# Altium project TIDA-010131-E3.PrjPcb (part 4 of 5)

## Sheet TIDA-010131-E3_USB.SchDoc: FT4232HQ_USB
size 431 x 279 mm; Date: Not shown in title block; ApprovedBy: Not shown in title block; CheckedBy: Not shown in title block; Author: Not shown in title block; CompanyName: Not shown in title block; DrawnBy: Avinash N; Engineer: Not shown in title block; Organization: Not shown in title block; Address1: Not shown in title block; Address2: Not shown in title block; Address3: Not shown in title block; Address4: Not shown in title block; DocumentNumber: 1; Revision: Use project parameter SCH_Rev; SheetNumber: 7; SheetTotal: 9; PageSetup: Record=PageOptions¦CenterHorizontal=True¦CenterVertical=True¦PrintScale=1.00¦XCorrection=1.00¦YCorrection=1.00¦PrintKind=0¦BorderSize=5000000¦LeftOffset=0¦BottomOffset=0¦Orientation=2¦PaperLength=1000¦PaperWidth=1000¦Scale=100¦PaperSource=15¦PrintQuality=600¦MediaType=1¦DitherType=10¦PaperKind=Letter¦PrintScaleMode=1
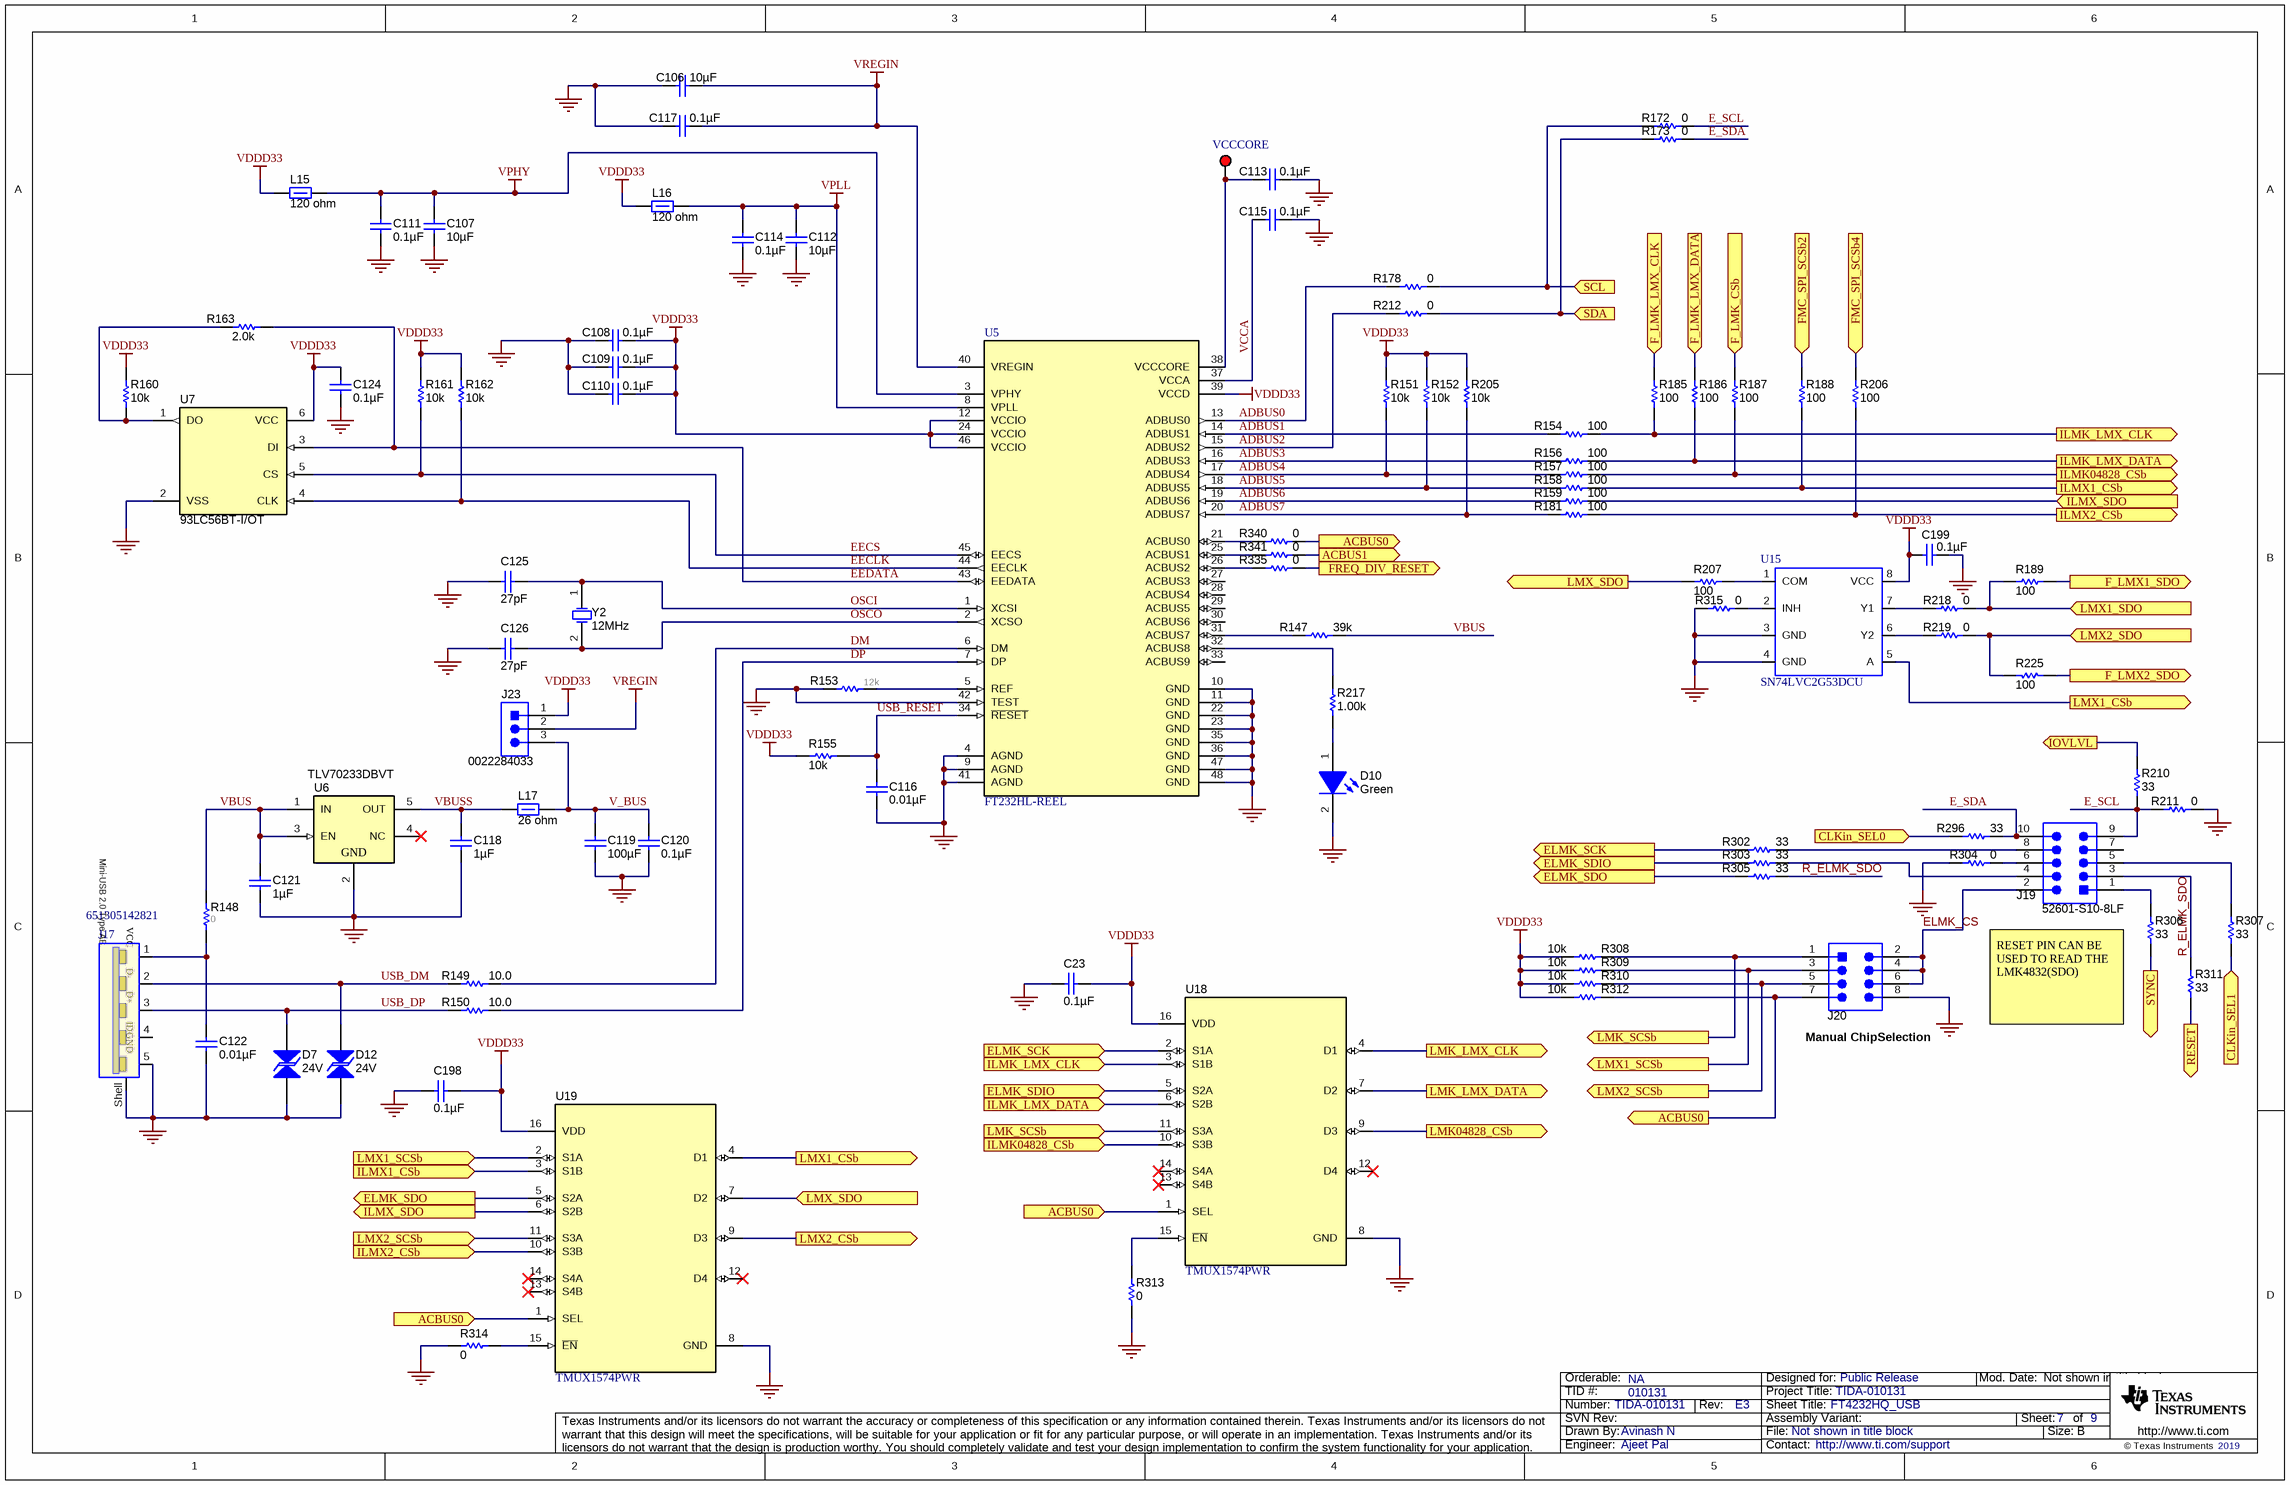
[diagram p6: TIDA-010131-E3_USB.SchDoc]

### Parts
C23  ValueDisplayed: 0.1µF  [0603]  (hidden comment: C0603C104J3RACTU)
C106  ValueDisplayed: 10µF  [0603]  (hidden comment: GRM188R61A106ME69D)
C107  ValueDisplayed: 10µF  [0603]  (hidden comment: GRM188R61A106ME69D)
C108  ValueDisplayed: 0.1µF  [0603]  (hidden comment: C0603C104J3RACTU)
C109  ValueDisplayed: 0.1µF  [0603]  (hidden comment: C0603C104J3RACTU)
C110  ValueDisplayed: 0.1µF  [0603]  (hidden comment: C0603C104J3RACTU)
C111  ValueDisplayed: 0.1µF  [0603]  (hidden comment: C0603C104J3RACTU)
C112  ValueDisplayed: 10µF  [0603]  (hidden comment: GRM188R61A106ME69D)
C113  ValueDisplayed: 0.1µF  [0603]  (hidden comment: C0603C104J3RACTU)
C114  ValueDisplayed: 0.1µF  [0603]  (hidden comment: C0603C104J3RACTU)
C115  ValueDisplayed: 0.1µF  [0603]  (hidden comment: C0603C104J3RACTU)
C116  ValueDisplayed: 0.01µF  [0402]  (hidden comment: GRM155R71E103KA01D)
C117  ValueDisplayed: 0.1µF  [0603]  (hidden comment: C0603C104J3RACTU)
C118  ValueDisplayed: 1µF  [0603]  (hidden comment: C1608X7R1C105K080AC)
C119  ValueDisplayed: 100µF  [1210_270]  (hidden comment: GRM32ER61A107ME20L)
C120  ValueDisplayed: 0.1µF  [0603]  (hidden comment: C0603C104J3RACTU)
C121  ValueDisplayed: 1µF  [0603]  (hidden comment: C1608X7R1C105K080AC)
C122  ValueDisplayed: 0.01µF  [0402]  (hidden comment: GRM155R71E103KA01D)
C124  ValueDisplayed: 0.1µF  [0603]  (hidden comment: C0603C104J3RACTU)
C125  ValueDisplayed: 27pF  [0603]  (hidden comment: GRM1885C2A270JA01D)
C126  ValueDisplayed: 27pF  [0603]  (hidden comment: GRM1885C2A270JA01D)
C198  ValueDisplayed: 0.1µF  [0603]  (hidden comment: C0603C104J3RACTU)
C199  ValueDisplayed: 0.1µF  [0603]  (hidden comment: C0603C104J3RACTU)
D7  value 24V  [PGB1_0603]  (hidden comment: PGB1010603MR)
D10  value Green  [LTST-C191_Green]  (hidden comment: LTST-C191TGKT)
D12  value 24V  [PGB1_0603]  (hidden comment: PGB1010603MR)
J17  651305142821  [651305142821]
J19  52601-S10-8LF  [FCI_52601-S10-8LF]
J20  TSW-104-07-G-D  [TSW-104-07-G-D]  (value not drawn)
J23  0022284033  [Molex_0022284033]
L15  ValueDisplayed: 120 ohm  [1206]  (hidden comment: BLM31PG121SN1L)
L16  ValueDisplayed: 120 ohm  [1206]  (hidden comment: BLM31PG121SN1L)
L17  ValueDisplayed: 26 ohm  [0603]  (hidden comment: BLM18SG260TN1D)
R147  ValueDisplayed: 39k  [0603]  (hidden comment: CRCW060339K0JNEA)
R148  value 0  [0603]  (hidden comment: CRCW06030000Z0EA)
R149  ValueDisplayed: 10.0  [0603]  (hidden comment: CRCW060310R0FKEAHP)
R150  ValueDisplayed: 10.0  [0603]  (hidden comment: CRCW060310R0FKEAHP)
R151  ValueDisplayed: 10k  [0603]  (hidden comment: CRCW060310K0JNEA)
R152  ValueDisplayed: 10k  [0603]  (hidden comment: CRCW060310K0JNEA)
R153  value 12k  [0603]  (hidden comment: CRCW060312K0JNEA)
R154  ValueDisplayed: 100  [0603]  (hidden comment: CRCW0603100RFKEA)
R155  ValueDisplayed: 10k  [0603]  (hidden comment: CRCW060310K0JNEA)
R156  ValueDisplayed: 100  [0603]  (hidden comment: CRCW0603100RFKEA)
R157  ValueDisplayed: 100  [0603]  (hidden comment: CRCW0603100RFKEA)
R158  ValueDisplayed: 100  [0603]  (hidden comment: CRCW0603100RFKEA)
R159  ValueDisplayed: 100  [0603]  (hidden comment: CRCW0603100RFKEA)
R160  ValueDisplayed: 10k  [0603]  (hidden comment: CRCW060310K0JNEA)
R161  ValueDisplayed: 10k  [0603]  (hidden comment: CRCW060310K0JNEA)
R162  ValueDisplayed: 10k  [0603]  (hidden comment: CRCW060310K0JNEA)
R163  ValueDisplayed: 2.0k  [0603]  (hidden comment: CRCW06032K00JNEA)
R172  ValueDisplayed: 0  [0402]  (hidden comment: CRCW04020000Z0ED)
R173  ValueDisplayed: 0  [0402]  (hidden comment: CRCW04020000Z0ED)
R178  ValueDisplayed: 0  [0603]  (hidden comment: CRCW06030000Z0EA)
R181  ValueDisplayed: 100  [0603]  (hidden comment: CRCW0603100RFKEA)
R185  ValueDisplayed: 100  [0603]  (hidden comment: CRCW0603100RFKEA)
R186  ValueDisplayed: 100  [0603]  (hidden comment: CRCW0603100RFKEA)
R187  ValueDisplayed: 100  [0603]  (hidden comment: CRCW0603100RFKEA)
R188  ValueDisplayed: 100  [0603]  (hidden comment: CRCW0603100RFKEA)
R189  ValueDisplayed: 100  [0603]  (hidden comment: CRCW0603100RFKEA)
R205  ValueDisplayed: 10k  [0603]  (hidden comment: CRCW060310K0JNEA)
R206  ValueDisplayed: 100  [0603]  (hidden comment: CRCW0603100RFKEA)
R207  ValueDisplayed: 100  [0603]  (hidden comment: CRCW0603100RFKEA)
R210  ValueDisplayed: 33  [0603]  (hidden comment: CRCW060333R0JNEA)
R211  ValueDisplayed: 0  [0603]  (hidden comment: CRCW06030000Z0EA)
R212  ValueDisplayed: 0  [0603]  (hidden comment: CRCW06030000Z0EA)
R217  ValueDisplayed: 1.00k  [0603]  (hidden comment: CRCW06031K00FKEA)
R218  ValueDisplayed: 0  [0402]  (hidden comment: CRCW04020000Z0ED)
R219  ValueDisplayed: 0  [0402]  (hidden comment: CRCW04020000Z0ED)
R225  ValueDisplayed: 100  [0603]  (hidden comment: CRCW0603100RFKEA)
R296  ValueDisplayed: 33  [0603]  (hidden comment: CRCW060333R0JNEA)
R302  ValueDisplayed: 33  [0603]  (hidden comment: CRCW060333R0JNEA)
R303  ValueDisplayed: 33  [0603]  (hidden comment: CRCW060333R0JNEA)
R304  ValueDisplayed: 0  [0603]  (hidden comment: CRCW06030000Z0EA)
R305  ValueDisplayed: 33  [0603]  (hidden comment: CRCW060333R0JNEA)
R306  ValueDisplayed: 33  [0603]  (hidden comment: CRCW060333R0JNEA)
R307  ValueDisplayed: 33  [0603]  (hidden comment: CRCW060333R0JNEA)
R308  ValueDisplayed: 10k  [0603]  (hidden comment: CRCW060310K0JNEA)
R309  ValueDisplayed: 10k  [0603]  (hidden comment: CRCW060310K0JNEA)
R310  ValueDisplayed: 10k  [0603]  (hidden comment: CRCW060310K0JNEA)
R311  ValueDisplayed: 33  [0603]  (hidden comment: CRCW060333R0JNEA)
R312  ValueDisplayed: 10k  [0603]  (hidden comment: CRCW060310K0JNEA)
R313  ValueDisplayed: 0  [0402]  (hidden comment: CRCW04020000Z0ED)
R314  ValueDisplayed: 0  [0402]  (hidden comment: CRCW04020000Z0ED)
R315  ValueDisplayed: 0  [0603]  (hidden comment: CRCW06030000Z0EA)
R335  ValueDisplayed: 0  [0402]  (hidden comment: CRCW04020000Z0ED)
R340  ValueDisplayed: 0  [0402]  (hidden comment: CRCW04020000Z0ED)
R341  ValueDisplayed: 0  [0402]  (hidden comment: CRCW04020000Z0ED)
U5  FT232HL-REEL  [LQFP-48_N]
U6  TLV70233DBVT  [DBV0005A_N]
U7  93LC56BT-I/OT  [SOT-23-6]
U15  SN74LVC2G53DCU  [VSSOP8]
U18  TMUX1574PWR  [PW0016A_N]
U19  TMUX1574PWR  [PW0016A_N]
VCCCORE  5000  [Keystone5000]  (value not drawn)
Y2  Frequency: 12MHz  [XTAL_ABM3]  (hidden comment: ABM3-12.000MHZ-B2-T)

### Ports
ACBUS0 (in), ACBUS0 (out), ACBUS1 (out), CLKin_SEL0 (in), CLKin_SEL1 (in), ELMK_SCK (in), ELMK_SCK (out), ELMK_SDIO (in), ELMK_SDIO (out), ELMK_SDO (out), F_LMK_CSb (in), F_LMK_LMX_CLK (in), F_LMK_LMX_DATA (in), F_LMX1_SDO (out), F_LMX2_SDO (out), FMC_SPI_SCSb2 (in), FMC_SPI_SCSb4 (in), FREQ_DIV_RESET (out), ILMK04828_CSb (in), ILMK04828_CSb (out), ILMK_LMX_CLK (in), ILMK_LMX_CLK (out), ILMK_LMX_DATA (in), ILMK_LMX_DATA (out), ILMX1_CSb (in), ILMX1_CSb (out), ILMX2_CSb (in), ILMX2_CSb (out), ILMX_SDO (in), ILMX_SDO (out), IOVLVL (out), LMK04828_CSb (out), LMK_LMX_CLK (out), LMK_LMX_DATA (out), LMK_SCSb (in), LMK_SCSb (out), LMX1_CSb (out), LMX1_SCSb (in), LMX1_SCSb (out), LMX1_SDO (in), LMX2_CSb (out), LMX2_SCSb (in), LMX2_SCSb (out), LMX2_SDO (in), LMX_SDO (in), LMX_SDO (out), RESET (out), SCL (in), SDA (in), SYNC (out)

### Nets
GND: C23.1 C106.2 C107.1 C108.2 C109.2 C110.2 C111.2 C112.2 C113.1 C114.2 C115.1 C116.2 C117.2 C118.2 C119.2 C120.1 C121.2 C122.2 C124.1 C125.1 C126.2 C198.1 C199.2 D7.1 D10.2(K) D12.1 J17.5(GND) J17.Shell J20.8 R153.2 R211.2 R304.1 R313.1 R314.1 R315.1 U5.4(AGND) U5.9(AGND) U5.10(GND) U5.11(GND) U5.22(GND) U5.23(GND) U5.35(GND) U5.36(GND) U5.41(AGND) U5.42(TEST) U5.47(GND) U5.48(GND) U6.2(GND) U7.2(VSS) U15.3(GND) U15.4(GND) U18.8(GND) U19.8(GND)
VDDD33: C23.2 C108.1 C109.1 C110.1 C124.2 C198.2 C199.1 J23.1 L15.1 L16.1 R151.2 R152.2 R155.2 R160.2 R161.2 R162.2 R205.2 R308.1 R309.1 R310.1 R312.1 U5.12(VCCIO) U5.24(VCCIO) U5.39(VCCD) U5.46(VCCIO) U7.6(VCC) U15.8(VCC) U18.16(VDD) U19.16(VDD)
VPHY: C107.2 C111.1 L15.2 U5.3(VPHY)
VPLL: C112.1 C114.1 L16.2 U5.8(VPLL)
VREGIN: C106.1 C117.1 J23.2 U5.40(VREGIN)
ACBUS0: J20.7 R312.2 R340.1 U18.1(SEL) U19.1(SEL) ; port ACBUS0
ACBUS1: R341.1 ; port ACBUS1
ADBUS0: R178.1 U5.13(ADBUS0)
ADBUS1: R154.1 U5.14(ADBUS1)
ADBUS2: R212.1 U5.15(ADBUS2)
ADBUS3: R156.1 U5.16(ADBUS3)
ADBUS4: R151.1 R157.1 U5.17(ADBUS4)
ADBUS5: R152.1 R158.1 U5.18(ADBUS5)
ADBUS6: R159.1 U5.19(ADBUS6)
ADBUS7: R181.1 R205.1 U5.20(ADBUS7)
CLKin_SEL0: R296.2 ; port CLKin_SEL0
CLKin_SEL1: R307.1 ; port CLKin_SEL1
DM: R149.2 U5.6(DM)
DP: R150.2 U5.7(DP)
E_SCL: J19.9 R172.2 R210.1 R211.1
E_SDA: J19.10 R173.2 R296.1
EECLK: R162.1 U5.44(EECLK) U7.4(CLK)
EECS: R161.1 U5.45(EECS) U7.5(CS)
EEDATA: R163.2 U5.43(EEDATA) U7.3(DI)
ELMK_CS: J19.2 J20.2 J20.4 J20.6
ELMK_SCK: R302.1 U18.2(S1A) ; port ELMK_SCK
ELMK_SDIO: R303.1 U18.5(S2A) ; port ELMK_SDIO
ELMK_SDO: R305.1 U19.5(S2A) ; port ELMK_SDO
F_LMK_CSb: R187.2 ; port F_LMK_CSb
F_LMK_LMX_CLK: R185.2 ; port F_LMK_LMX_CLK
F_LMK_LMX_DATA: R186.2 ; port F_LMK_LMX_DATA
F_LMX1_SDO: R189.2 ; port F_LMX1_SDO
F_LMX2_SDO: R225.2 ; port F_LMX2_SDO
FMC_SPI_SCSb2: R188.2 ; port FMC_SPI_SCSb2
FMC_SPI_SCSb4: R206.2 ; port FMC_SPI_SCSb4
FREQ_DIV_RESET: R335.1 ; port FREQ_DIV_RESET
ILMK04828_CSb: R157.2 R187.1 U18.10(S3B) ; port ILMK04828_CSb
ILMK_LMX_CLK: R154.2 R185.1 U18.3(S1B) ; port ILMK_LMX_CLK
ILMK_LMX_DATA: R156.2 R186.1 U18.6(S2B) ; port ILMK_LMX_DATA
ILMX1_CSb: R158.2 R188.1 U19.3(S1B) ; port ILMX1_CSb
ILMX2_CSb: R181.2 R206.1 U19.10(S3B) ; port ILMX2_CSb
ILMX_SDO: R159.2 U19.6(S2B) ; port ILMX_SDO
IOVLVL: R210.2 ; port IOVLVL
LMK04828_CSb: U18.9(D3) ; port LMK04828_CSb
LMK_LMX_CLK: U18.4(D1) ; port LMK_LMX_CLK
LMK_LMX_DATA: U18.7(D2) ; port LMK_LMX_DATA
LMK_SCSb: J20.1 R308.2 U18.11(S3A) ; port LMK_SCSb
LMX1_CSb: U15.5(A) U19.4(D1) ; port LMX1_CSb
LMX1_SCSb: J20.3 R309.2 U19.2(S1A) ; port LMX1_SCSb
LMX1_SDO: R189.1 R218.2 ; port LMX1_SDO
LMX2_CSb: U19.9(D3) ; port LMX2_CSb
LMX2_SCSb: J20.5 R310.2 U19.11(S3A) ; port LMX2_SCSb
LMX2_SDO: R219.2 R225.1 ; port LMX2_SDO
LMX_SDO: R207.2 U19.7(D2) ; port LMX_SDO
OSCI: C125.2 U5.1(XCSI) Y2.1(OSC1)
OSCO: C126.1 U5.2(XCSO) Y2.2(OSC2)
R_ELMK_SDO: J19.3 R305.2 R311.2
RESET: R311.1 ; port RESET
SCL: R172.1 R178.2 ; port SCL
SDA: R173.1 R212.2 ; port SDA
SYNC: R306.1 ; port SYNC
USB_DM: D12.2 J17.2(D-) R149.1
USB_DP: D7.2 J17.3(D+) R150.1
USB_RESET: C116.1 R155.1 U5.34(~{RESET})
V_BUS: C119.1 C120.2 J23.3 L17.2
VBUS: C121.1 R147.2 R148.2 U6.1(IN) U6.3(EN)
VBUSS: C118.1 L17.1 U6.5(OUT)
VCCA: C115.2 U5.37(VCCA)
NetC113_2: C113.2 U5.38(VCCCORE) VCCCORE.1
NetC122_1: C122.1 J17.1(VCC) R148.1
NetD10_1: D10.1(A) R217.1
NetJ19_1: J19.1 R306.2
NetJ19_4: J19.4 R303.2
NetJ19_5: J19.5 R307.2
NetJ19_6: J19.6 R304.2
NetJ19_8: J19.8 R302.2
NetR147_1: R147.1 U5.31(ACBUS7)
NetR153_1: R153.1 U5.5(REF)
NetR160_1: R160.1 R163.1 U7.1(DO)
NetR207_1: R207.1 U15.1(COM)
NetR217_2: R217.2 U5.32(ACBUS8)
NetR218_1: R218.1 U15.7(Y1)
NetR219_1: R219.1 U15.6(Y2)
NetR313_2: R313.2 U18.15(~{EN})
NetR314_2: R314.2 U19.15(~{EN})
NetR315_2: R315.2 U15.2(INH)
NetR335_2: R335.2 U5.26(ACBUS2)
NetR340_2: R340.2 U5.21(ACBUS0)
NetR341_2: R341.2 U5.25(ACBUS1)

Not connected (* = marked no-connect by the designer): J17 4(ID); J19 7; U5 27(ACBUS3) 28(ACBUS4) 29(ACBUS5) 30(ACBUS6) 33(ACBUS9); U6 4(NC)*; U18 12(D4)* 13(S4B)* 14(S4A)*; U19 12(D4)* 13(S4B)* 14(S4A)*

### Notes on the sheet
- (near J20) Manual ChipSelection
- RESET PIN CAN BE USED TO READ THE LMK4832(SDO)

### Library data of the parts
C23 C108-C111 C113-C115 C117 C120 C124 C198 C199 = C0603C104J3RACTU: CAP, CERM, 0.1uF, 25V, +/-5%, X7R, 0603; Manufacturer: Kemet; Polarized: N; TaMax_C: 125; TaMin_C: -55; Tolerance_%: 5; VDC_V: 25; Cap_F: 0.0000001; CompType: Capacitor; Value1: Unknown; U/M: EA
C106 C107 C112 = GRM188R61A106ME69D: CAP, CERM, 10 µF, 10 V, +/- 20%, X5R, 0603; Manufacturer: MuRata; Polarized: N; CompType: Capacitor; Value: 10uF; U/M: EA; Cap_F: 0.00001; Tolerance_%: 20; Value1: Unknown; VDC_V: 10; Value2: 10V; TaMin_C: -55; TaMax_C: 85; SizeArea_mm2: 1.28; SizeAreaWB_mm2: 4.68; SizeX_mm: 1.6; SizeY_mm: 0.8; SizeZ_mm: 1; AEC Category: Q200
C116 C122 = GRM155R71E103KA01D: CAP, CERM, 0.01 µF, 25 V, +/- 10%, X7R, 0402; Manufacturer: MuRata; Polarized: N; CompType: Capacitor; Value: 0.01uF; U/M: EA; Cap_F: 0.00000001; Tolerance_%: 10; Value1: Unknown; VDC_V: 25; Value2: 25V; TaMin_C: -55; TaMax_C: 125; SizeArea_mm2: 0.5; SizeAreaWB_mm2: 3; SizeX_mm: 1; SizeZ_mm: 0.6; AEC Category: Q200
C118 C121 = C1608X7R1C105K080AC: CAP, CERM, 1 µF, 16 V, +/- 10%, X7R, 0603; Manufacturer: TDK; Polarized: N; CompType: Capacitor; Value: 1uF; U/M: EA; Cap_F: 0.000001; Tolerance_%: 10; ESR_ohm: 0.0057; Value1: 0.0057 ohm; VDC_V: 16; Value2: 16V; TaMin_C: -55; TaMax_C: 125; SizeArea_mm2: 1.28; SizeAreaWB_mm2: 4.68; SizeX_mm: 1.6; SizeY_mm: 0.8; SizeZ_mm: 1; AEC Category: Q200
C119 = GRM32ER61A107ME20L: CAP, CERM, 100 µF, 10 V, +/- 20%, X5R, 1210; Manufacturer: MuRata; Polarized: N; CompType: Capacitor; Value: 100uF; U/M: EA; Cap_F: 0.0001; Tolerance_%: 20; Value1: Unknown; VDC_V: 10; Value2: 10V; TaMin_C: -55; TaMax_C: 85; Cap_Case: 1210; SizeArea_mm2: 8; SizeAreaWB_mm2: 14.7; SizeX_mm: 3.2; SizeY_mm: 2.5; SizeZ_mm: 2.7; AEC Category: Q200
C125 C126 = GRM1885C2A270JA01D: CAP, CERM, 27 pF, 100 V, +/- 5%, C0G/NP0, 0603; Manufacturer: MuRata; Polarized: N; CompType: Capacitor; Value: 27pF; U/M: EA; Cap_F: 0.000000000027; Tolerance_%: 5; Value1: Unknown; VDC_V: 100; Value2: 100V; TaMin_C: -55; TaMax_C: 125; SizeArea_mm2: 1.28; SizeAreaWB_mm2: 4.68; SizeX_mm: 1.6; SizeY_mm: 0.8; SizeZ_mm: 1; AEC Category: Q200
D7 D12 = PGB1010603MR: PulseGuard ESD Suppressor, 24VDC, SMT; Manufacturer: Littelfuse
D10 = LTST-C191TGKT: LED, Green, SMD; Manufacturer: Lite-On; Type: InGaN; Vf_V: 3.2; Value2: 3.2V; Io_A: 0.02; Value1: W; U/M: EA
J17 = 651305142821: WR-COM Mini USB 2.0 Type AB SMT Horizontal 5 Contacts
J19 = 52601-S10-8LF: Header (shrouded), 100mil, 5x2, Gold, SMT; Manufacturer: FCI; SymbolCreator: a0412235
J20 = TSW-104-07-G-D: Header, 100mil, 4x2, Gold, TH; Manufacturer: Samtec; SymbolCreator: a0411947; Pitch_mm: 2.54; Gender: Male; Shrouded: N; Row_Count: 2; Current_A: 6.3; Voltage_V: 550; Cert_CSA: Y
J23 = 0022284033: Header, 2.54mm, 3x1, Tin, TH; Manufacturer: Molex; SymbolCreator: a0799628; Pitch_mm: 2.54; Gender: Male; Shrouded: N; Row_Count: 1; Current_A: 4; Voltage_V: 250; Cert_UL: Y
L15 L16 = BLM31PG121SN1L: Ferrite Bead, 120 ohm @ 100 MHz, 3.5 A, 1206; Manufacturer: MuRata; Value: 120 ohm; Imax_A: 3.5; DCR_ohm: 0.02; Value1: 0.02 ohm; Value2: 3.5A; SizeAreaWB_mm2: 10.92; SizeArea_mm2: 5.12; SizeX_mm: 3.2; SizeY_mm: 1.6; SizeZ_mm: 1.35; ZTyp@100MHz_Ohm: 120
L17 = BLM18SG260TN1D: Ferrite Bead, 26 ohm @ 100 MHz, 6 A, 0603; Manufacturer: MuRata; Value: 26 ohm; Imax_A: 6; DCR_ohm: 0.007; Value1: 0.007 ohm; Value2: 6A; SizeAreaWB_mm2: 4.68; SizeArea_mm2: 1.28; SizeX_mm: 1.6; SizeY_mm: 0.8; SizeZ_mm: 1; ZTyp@100MHz_Ohm: 26
R147 = CRCW060339K0JNEA: RES, 39 k, 5%, 0.1 W, 0603; Manufacturer: Vishay-Dale; CompType: Resistor; Value: 39k; Res_ohm: 39000; Value_Code: 39k0; Tolerance_%: 5; Power_W: 0.1; Value2: 0.1W; VDC_V: 75; TempCo: 200 ppm/C; SizeArea_mm2: 1.28; SizeX_mm: 1.6; SizeY_mm: 0.8; SizeZ_mm: 1; EIA_Code: E24; U/M: EA; AEC Category: Q200
R148 = CRCW06030000Z0EA: RES, 0 ohm, 5%, 0.1W, 0603; Manufacturer: Vishay-Dale; CompType: Resistor; Tolerance_%: 5; VDC_V: 75; Power_W: 0.1; U/M: EA; Value_Code: 0000; EIA_Code: E24
R149 R150 = CRCW060310R0FKEAHP: RES, 10.0, 1%, 0.25 W, 0603; Manufacturer: Vishay-Dale; CompType: Resistor; Value: 10.0; Res_ohm: 10; Value_Code: 10R0; Tolerance_%: 1; Power_W: 0.25; Value2: 0.25W; VDC_V: 75; TempCo: 100 ppm/C; SizeArea_mm2: 1.28; SizeX_mm: 1.6; SizeY_mm: 0.8; EIA_Code: E96; U/M: EA; AEC Category: Q200
R151 R152 R155 R160-R162 R205 R308-R310 R312 = CRCW060310K0JNEA: RES, 10 k, 5%, 0.1 W, 0603; Manufacturer: Vishay-Dale; CompType: Resistor; Value: 10k; Res_ohm: 10000; Value_Code: 10k0; Tolerance_%: 5; Power_W: 0.1; Value2: 0.1W; VDC_V: 75; TempCo: 200 ppm/C; SizeArea_mm2: 1.28; SizeX_mm: 1.6; SizeY_mm: 0.8; SizeZ_mm: 1; EIA_Code: E24; U/M: EA; AEC Category: Q200
R153 = CRCW060312K0JNEA: RES, 12k ohm, 5%, 0.1W, 0603; Manufacturer: Vishay-Dale; CompType: Resistor; Tolerance_%: 5; VDC_V: 75; Power_W: 0.1; Res_ohm: 12000; U/M: EA; Value_Code: 12k0; EIA_Code: E24
R154 R156-R159 R181 R185-R189 R206 R207 R225 = CRCW0603100RFKEA: RES, 100, 1%, 0.1 W, 0603; Manufacturer: Vishay-Dale; CompType: Resistor; Value: 100; Value_Code: 100R; Tolerance_%: 1; Power_W: 0.1; Value2: 0.1W; VDC_V: 75; TempCo: 100 ppm/C; SizeArea_mm2: 1.28; SizeX_mm: 1.6; SizeY_mm: 0.8; EIA_Code: E96; U/M: EA; AEC Category: Q200
R163 = CRCW06032K00JNEA: RES, 2.0 k, 5%, 0.1 W, 0603; Manufacturer: Vishay-Dale; CompType: Resistor; Value: 2.0k; Res_ohm: 2000; Value_Code: 2k00; Tolerance_%: 5; Power_W: 0.1; Value2: 0.1W; VDC_V: 75; TempCo: 200 ppm/C; SizeArea_mm2: 1.28; SizeX_mm: 1.6; SizeY_mm: 0.8; SizeZ_mm: 1; EIA_Code: E24; U/M: EA; AEC Category: Q200
R172 R173 R218 R219 R313 R314 = CRCW04020000Z0ED: RES, 0, 5%, 0.063 W, 0402; Manufacturer: Vishay-Dale; CompType: Resistor; Value: 0; Value_Code: 0000; Tolerance_%: 5; Power_W: 0.063; Value2: 0.063W; VDC_V: 50; TempCo: 200 ppm/C; SizeArea_mm2: 0.5; SizeX_mm: 1; SizeZ_mm: 0.6; EIA_Code: E24; U/M: EA; AEC Category: Q200
R178 R212 = CRCW06030000Z0EA: RES, 0, 5%, 0.1 W, 0603; Manufacturer: Vishay-Dale; CompType: Resistor; Value: 0; Value_Code: 0000; Tolerance_%: 5; Power_W: 0.1; Value2: 0.1W; VDC_V: 75; TempCo: 200 ppm/C; SizeArea_mm2: 1.28; SizeX_mm: 1.6; SizeY_mm: 0.8; SizeZ_mm: 1; EIA_Code: E24; U/M: EA; AEC Category: Q200; Green_Lifecycle: Active; Green_REACh: Passed
R210 R296 R302 R303 R305-R307 R311 = CRCW060333R0JNEA: RES, 33, 5%, 0.1 W, 0603; Manufacturer: Vishay-Dale; CompType: Resistor; Value: 33; Value_Code: 33R0; Tolerance_%: 5; Power_W: 0.1; Value2: 0.1W; VDC_V: 75; TempCo: 200 ppm/C; SizeArea_mm2: 1.28; SizeX_mm: 1.6; SizeY_mm: 0.8; SizeZ_mm: 1; EIA_Code: E24; U/M: EA; AEC Category: Q200
R211 R304 R315 = CRCW06030000Z0EA: RES, 0, 5%, 0.1 W, 0603; Manufacturer: Vishay-Dale; CompType: Resistor; Value: 0; Value_Code: 0000; Tolerance_%: 5; Power_W: 0.1; Value2: 0.1W; VDC_V: 75; TempCo: 200 ppm/C; SizeArea_mm2: 1.28; SizeX_mm: 1.6; SizeY_mm: 0.8; SizeZ_mm: 1; EIA_Code: E24; U/M: EA; AEC Category: Q200
R217 = CRCW06031K00FKEA: RES, 1.00 k, 1%, 0.1 W, 0603; Manufacturer: Vishay-Dale; CompType: Resistor; Value: 1.00k; Res_ohm: 1000; Value_Code: 1k00; Tolerance_%: 1; Power_W: 0.1; Value2: 0.1W; VDC_V: 75; TempCo: 100 ppm/C; SizeArea_mm2: 1.28; SizeX_mm: 1.6; SizeY_mm: 0.8; EIA_Code: E96; U/M: EA; AEC Category: Q200
R335 R340 R341 = CRCW04020000Z0ED: RES, 0, 5%, 0.063 W, 0402; Manufacturer: Vishay-Dale; CompType: Resistor; Tolerance_%: 5; VDC_V: 50; Power_W: 0.063; Value: 0; U/M: EA; Value_Code: 0000; Value2: 0.063W; EIA_Code: E24; TempCo: 200 ppm/C; SizeArea_mm2: 0.5; SizeX_mm: 1; SizeZ_mm: 0.6; AEC Category: Q200; Green_Lifecycle: Active; Green_REACh: Passed
U5 = FT232HL-REEL: Single Channel Hi-Speed USB to Multipurpose UART/FIFO IC, LQFP-48; Manufacturer: FTDI; SymbolCreator: Altium
U6 = TLV70233DBVT: Single Output LDO, 300 mA, Fixed 3.3 V Output, 2 to 5.5 V Input, with Low IQ, 5-pin SOT-23 (DBV), -40 to 125 degC, Green (RoHS & no Sb/Br); Manufacturer: Texas Instruments; Alternate PartNumber: Equivalent; Accuracy(%): 2; Fixed Output Options(V): 3.3; Iout(Max)(A): 0.3; Iq(Typ)(mA): 0.03; SubFamily: Single Channel LDO; Vdo(Typ)(mV): 220; Vin(Max)(V): 5.5
U7 = 93LC56BT-I/OT: 2K Microwire Compatible Serial EEPROM, SOT-23-6; Manufacturer: Microchip; SymbolCreator: x0208326; SizeAreaWB_mm2: 14.82; SizeArea_mm2: 8.12; SizeX_mm: 2.9; SizeY_mm: 2.8; SizeZ_mm: 1.15
U15 = SN74LVC2G53DCU: IC, SPDT Analog Switch; Manufacturer: TI; Alternate Manufacturer: None; Area: 36735
U18 U19 = CMP-0086166-2: Low-capacitance, 2:1 (SPDT) 4-channel, powered-off protection switch with 1.8 V logic, PW0016A (TSSOP-16); Alternate Manufacturer: Texas Instruments; Alternate PartNumber: SN74CBTLV3257PWR; AEC Qualified: N; Rating: Catalog; SizeZ_mm: 1.2; CompType: IC; SizeArea_mm2: 32; AEC Category: Q200; SizeY_mm: 5; SizeAreaWB_mm2: 58.8; SizeX_mm: 6.4
VCCCORE = 5000: Test Point, Miniature, Red, TH; Manufacturer: Keystone; CompType: Test Point Loop; ContactFinish: Silver
Y2 = ABM3-12.000MHZ-B2-T: Crystal, 12Mhz, 18pF, SMD; Manufacturer: Abracon Corporation; SymbolCreator: a0412235; U/M: EA; TaMin_C: -20; TaMax_C: 70; Frequency Stability: ±50ppm

## Sheet TIDA-010131-E3_POWER SUPPLIES.SchDoc: POWER SUPPLIES
size 431 x 279 mm; Date: Not shown in title block; ApprovedBy: Not shown in title block; CheckedBy: Not shown in title block; Author: Not shown in title block; CompanyName: Not shown in title block; DrawnBy: Avinash N; Engineer: Not shown in title block; Organization: Not shown in title block; Address1: Not shown in title block; Address2: Not shown in title block; Address3: Not shown in title block; Address4: Not shown in title block; DocumentNumber: 1; Revision: Use project parameter SCH_Rev; SheetNumber: 8; SheetTotal: 9; PageSetup: Record=PageOptions¦CenterHorizontal=True¦CenterVertical=True¦PrintScale=1.00¦XCorrection=1.00¦YCorrection=1.00¦PrintKind=0¦BorderSize=5000000¦LeftOffset=0¦BottomOffset=0¦Orientation=2¦PaperLength=1000¦PaperWidth=1000¦Scale=100¦PaperSource=15¦PrintQuality=600¦MediaType=1¦DitherType=10¦PaperKind=Letter¦PrintScaleMode=1
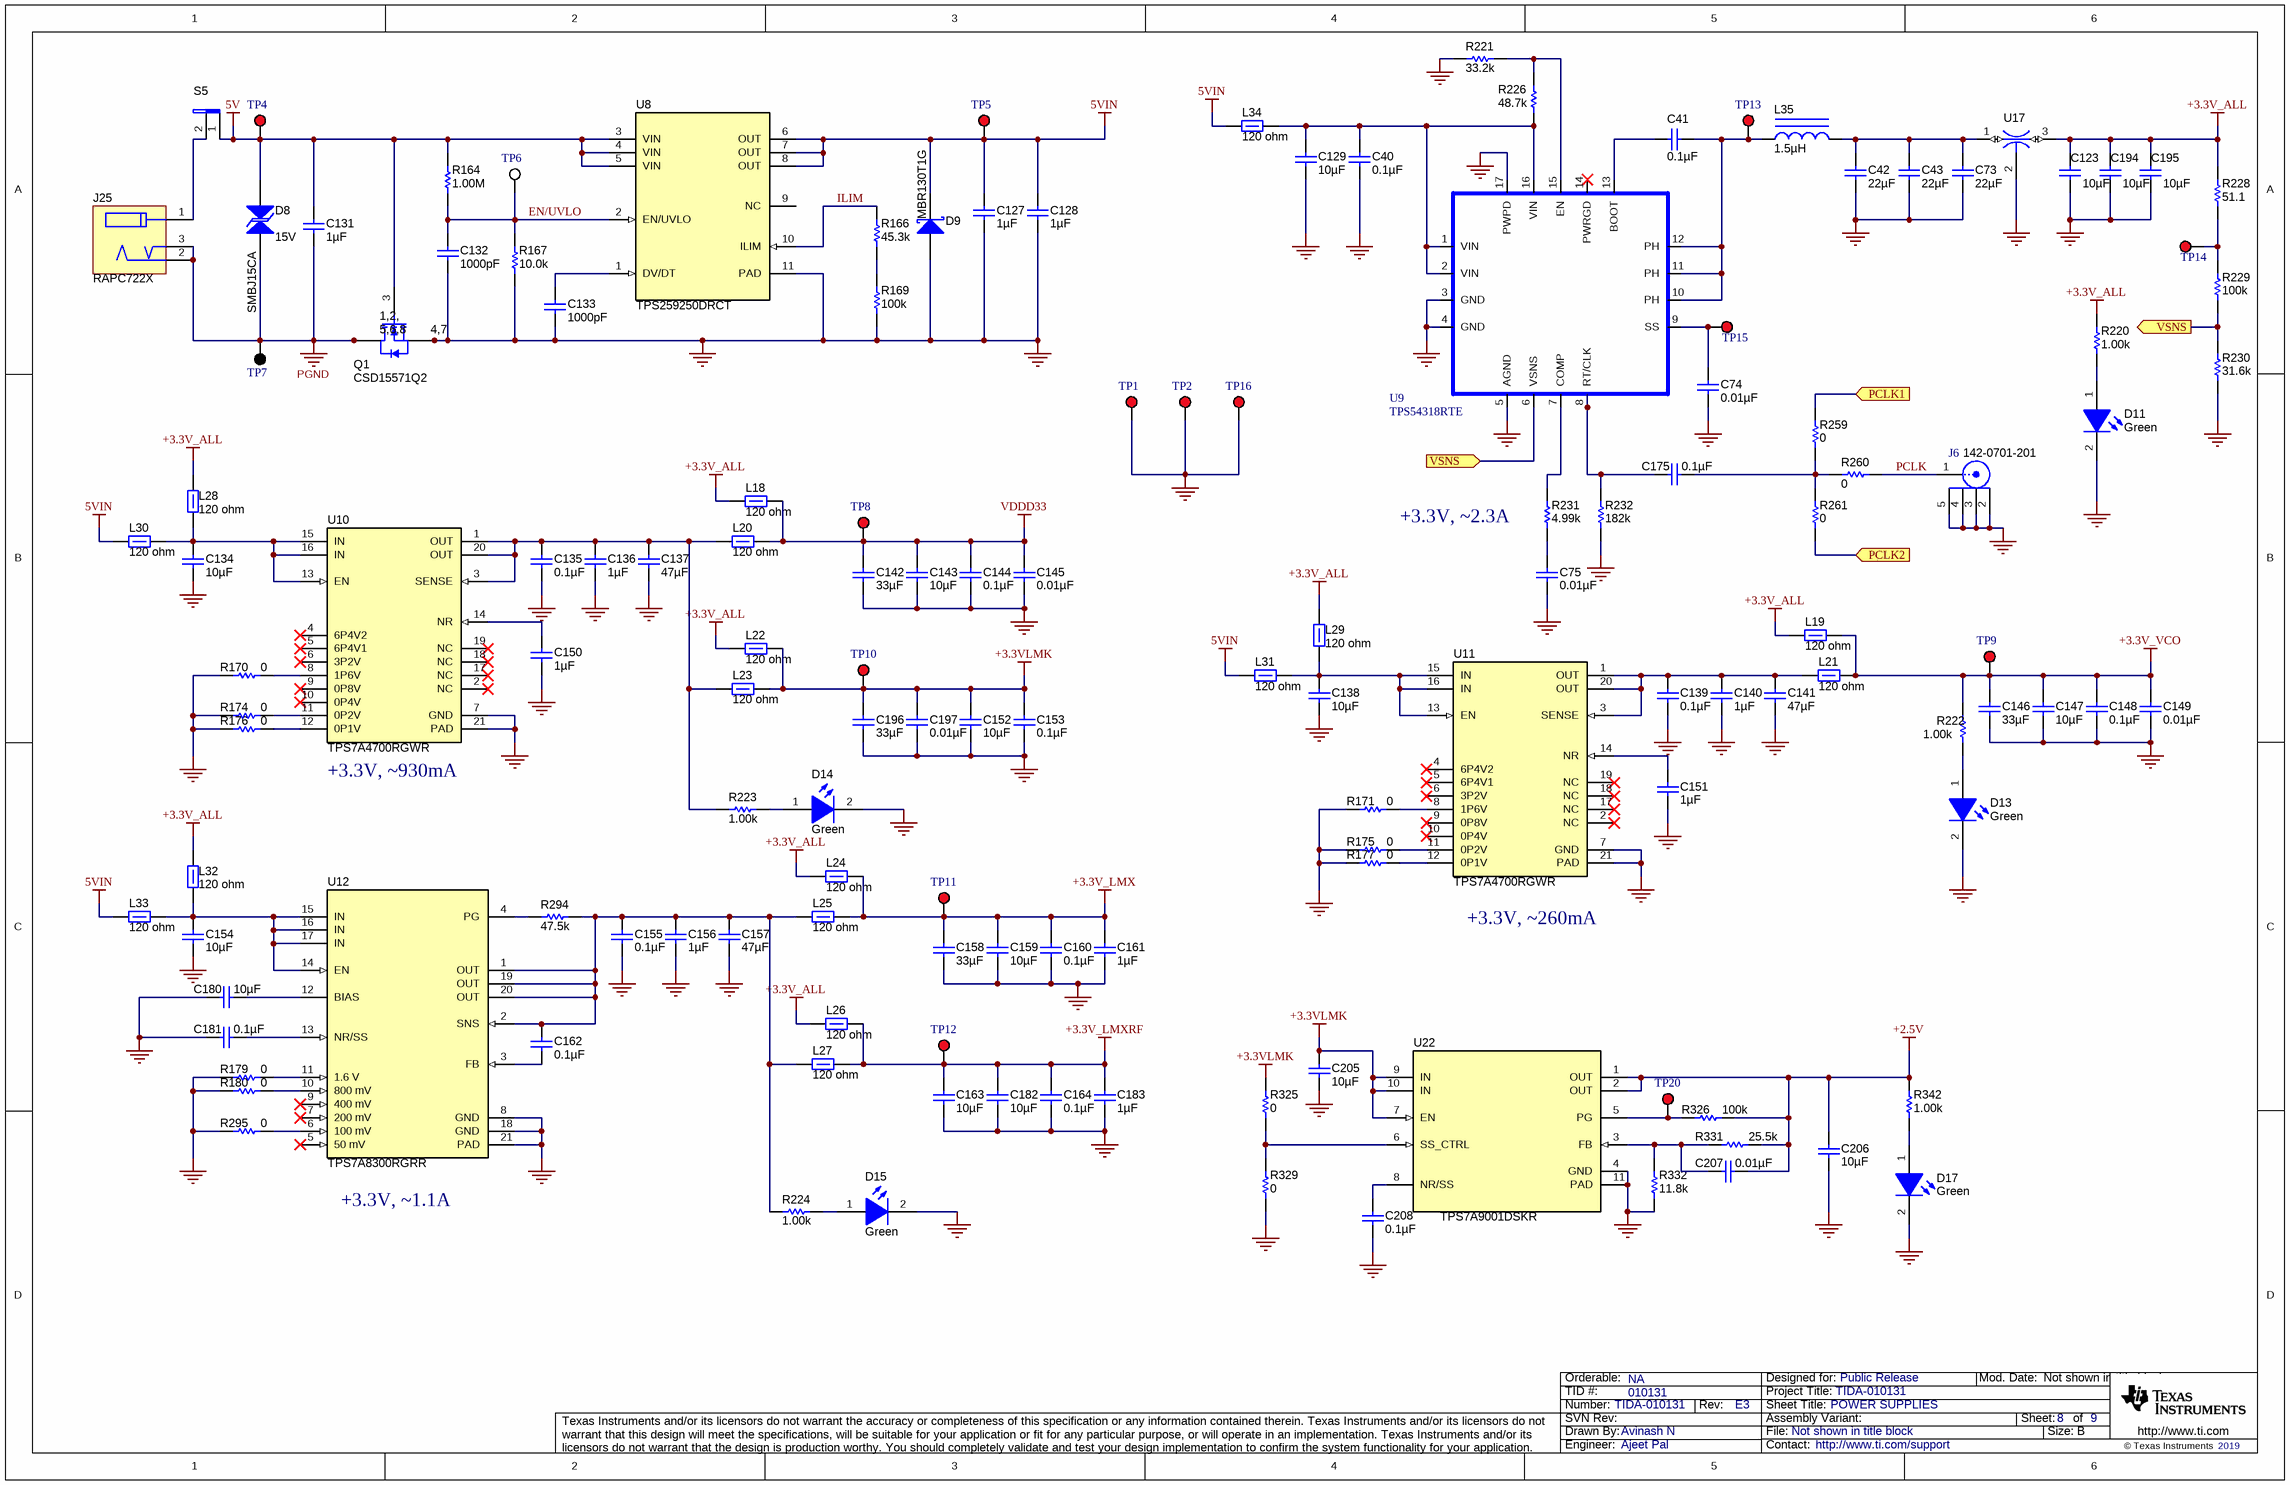
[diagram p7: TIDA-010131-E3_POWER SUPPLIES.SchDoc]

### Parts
C40  ValueDisplayed: 0.1µF  [0402]  (hidden comment: GRM155R71C104KA88D)
C41  ValueDisplayed: 0.1µF  [0402]  (hidden comment: GRM155R71C104KA88D)
C42  ValueDisplayed: 22µF  [1206_190]  (hidden comment: 885012208019)
C43  ValueDisplayed: 22µF  [1206_190]  (hidden comment: 885012208019)
C73  ValueDisplayed: 22µF  [1206_190]  (hidden comment: 885012208019)
C74  ValueDisplayed: 0.01µF  [0402]  (hidden comment: GRM155R71E103KA01D)
C75  ValueDisplayed: 0.01µF  [0603]  (hidden comment: GRM188R71E103KA01D)
C123  ValueDisplayed: 10µF  [0603]  (hidden comment: GRM188R61A106ME69D)
C127  ValueDisplayed: 1µF  [0805_HV]  (hidden comment: 08053D105KAT2A)
C128  ValueDisplayed: 1µF  [0805_HV]  (hidden comment: 08053D105KAT2A)
C129  ValueDisplayed: 10µF  [0603]  (hidden comment: GRM188R61A106ME69D)
C131  ValueDisplayed: 1µF  [0805_HV]  (hidden comment: 08053D105KAT2A)
C132  ValueDisplayed: 1000pF  [0603]  (hidden comment: 06031C102MAT2A)
C133  ValueDisplayed: 1000pF  [0603]  (hidden comment: 06031C102MAT2A)
C134  ValueDisplayed: 10µF  [0603]  (hidden comment: GRM188R61A106ME69D)
C135  ValueDisplayed: 0.1µF  [0402]  (hidden comment: GRM155R71C104KA88D)
C136  ValueDisplayed: 1µF  [0402]  (hidden comment: C1005X7S1A105K050BC)
C137  ValueDisplayed: 47µF  [1210_280]  (hidden comment: C3225X5R1A476M250AC)
C138  ValueDisplayed: 10µF  [0603]  (hidden comment: GRM188R61A106ME69D)
C139  ValueDisplayed: 0.1µF  [0402]  (hidden comment: GRM155R71C104KA88D)
C140  ValueDisplayed: 1µF  [0402]  (hidden comment: C1005X7S1A105K050BC)
C141  ValueDisplayed: 47µF  [1210_280]  (hidden comment: C3225X5R1A476M250AC)
C142  ValueDisplayed: 33µF  [0805_HV]  (hidden comment: C2012X5R1A336M125AC)
C143  ValueDisplayed: 10µF  [0603]  (hidden comment: GRM188R61A106ME69D)
C144  ValueDisplayed: 0.1µF  [0402]  (hidden comment: GRM155R71C104KA88D)
C145  ValueDisplayed: 0.01µF  [0402]  (hidden comment: GRM155R71E103KA01D)
C146  ValueDisplayed: 33µF  [0805_HV]  (hidden comment: C2012X5R1A336M125AC)
C147  ValueDisplayed: 10µF  [0603]  (hidden comment: GRM188R61A106ME69D)
C148  ValueDisplayed: 0.1µF  [0402]  (hidden comment: GRM155R71C104KA88D)
C149  ValueDisplayed: 0.01µF  [0402]  (hidden comment: GRM155R71E103KA01D)
C150  ValueDisplayed: 1µF  [0402]  (hidden comment: C1005X7S1A105K050BC)
C151  ValueDisplayed: 1µF  [0402]  (hidden comment: C1005X7S1A105K050BC)
C152  ValueDisplayed: 10µF  [0603]  (hidden comment: GRM188R61A106ME69D)
C153  ValueDisplayed: 0.1µF  [0402]  (hidden comment: GRM155R71C104KA88D)
C154  ValueDisplayed: 10µF  [0603]  (hidden comment: GRM188R61A106ME69D)
C155  ValueDisplayed: 0.1µF  [0402]  (hidden comment: GRM155R71C104KA88D)
C156  ValueDisplayed: 1µF  [0402]  (hidden comment: C1005X7S1A105K050BC)
C157  ValueDisplayed: 47µF  [1210_280]  (hidden comment: C3225X5R1A476M250AC)
C158  ValueDisplayed: 33µF  [0805_HV]  (hidden comment: C2012X5R1A336M125AC)
C159  ValueDisplayed: 10µF  [0603]  (hidden comment: GRM188R61A106ME69D)
C160  ValueDisplayed: 0.1µF  [0402]  (hidden comment: GRM155R71C104KA88D)
C161  ValueDisplayed: 1µF  [0402]  (hidden comment: C1005X7S1A105K050BC)
C162  ValueDisplayed: 0.1µF  [0402]  (hidden comment: GRM155R71C104KA88D)
C163  ValueDisplayed: 10µF  [0603]  (hidden comment: GRM188R61A106ME69D)
C164  ValueDisplayed: 0.1µF  [0402]  (hidden comment: GRM155R71C104KA88D)
C175  ValueDisplayed: 0.1µF  [0402]  (hidden comment: GRM155R71C104KA88D)
C180  ValueDisplayed: 10µF  [0603]  (hidden comment: GRM188R61A106ME69D)
C181  ValueDisplayed: 0.1µF  [0402]  (hidden comment: GRM155R71C104KA88D)
C182  ValueDisplayed: 10µF  [0603]  (hidden comment: GRM188R61A106ME69D)
C183  ValueDisplayed: 1µF  [0402]  (hidden comment: C1005X7S1A105K050BC)
C194  ValueDisplayed: 10µF  [0603]  (hidden comment: GRM188R61A106ME69D)
C195  ValueDisplayed: 10µF  [0603]  (hidden comment: GRM188R61A106ME69D)
C196  ValueDisplayed: 33µF  [0805_HV]  (hidden comment: C2012X5R1A336M125AC)
C197  ValueDisplayed: 0.01µF  [0402]  (hidden comment: GRM155R71E103KA01D)
C205  ValueDisplayed: 10µF  [0603]  (hidden comment: GRM188R61C106MAALD)
C206  ValueDisplayed: 10µF  [0603]  (hidden comment: GRM188R61C106MAALD)
C207  ValueDisplayed: 0.01µF  [0603]  (hidden comment: GRM188R71C103KA01D)
C208  ValueDisplayed: 0.1µF  [0603]  (hidden comment: CL10B104KO8NNNC)
D8  SMBJ15CA  value 15V  [SMB-Bi]
D9  MBR130T1G  [SOD-123]
D11  value Green  [LTST-C191_Green]  (hidden comment: LTST-C191TGKT)
D13  value Green  [LTST-C191_Green]  (hidden comment: LTST-C191TGKT)
D14  value Green  [LTST-C191_Green]  (hidden comment: LTST-C191TGKT)
D15  value Green  [LTST-C191_Green]  (hidden comment: LTST-C191TGKT)
D17  value Green  [LTST-C191_Green]  (hidden comment: LTST-C191TGKT)
J6  142-0701-201  [Johnson_142-0701-20x]
J25  RAPC722X  [CONN_RAPC722X]
L18  ValueDisplayed: 120 ohm  [1206]  (hidden comment: BLM31PG121SN1L)
L19  ValueDisplayed: 120 ohm  [1206]  (hidden comment: BLM31PG121SN1L)
L20  ValueDisplayed: 120 ohm  [1206]  (hidden comment: BLM31PG121SN1L)
L21  ValueDisplayed: 120 ohm  [1206]  (hidden comment: BLM31PG121SN1L)
L22  ValueDisplayed: 120 ohm  [1206]  (hidden comment: BLM31PG121SN1L)
L23  ValueDisplayed: 120 ohm  [1206]  (hidden comment: BLM31PG121SN1L)
L24  ValueDisplayed: 120 ohm  [1206]  (hidden comment: BLM31PG121SN1L)
L25  ValueDisplayed: 120 ohm  [1206]  (hidden comment: BLM31PG121SN1L)
L26  ValueDisplayed: 120 ohm  [1206]  (hidden comment: BLM31PG121SN1L)
L27  ValueDisplayed: 120 ohm  [1206]  (hidden comment: BLM31PG121SN1L)
L28  ValueDisplayed: 120 ohm  [1206]  (hidden comment: BLM31PG121SN1L)
L29  ValueDisplayed: 120 ohm  [1206]  (hidden comment: BLM31PG121SN1L)
L30  ValueDisplayed: 120 ohm  [1206]  (hidden comment: BLM31PG121SN1L)
L31  ValueDisplayed: 120 ohm  [1206]  (hidden comment: BLM31PG121SN1L)
L32  ValueDisplayed: 120 ohm  [1206]  (hidden comment: BLM31PG121SN1L)
L33  ValueDisplayed: 120 ohm  [1206]  (hidden comment: BLM31PG121SN1L)
L34  ValueDisplayed: 120 ohm  [1206]  (hidden comment: BLM31PG121SN1L)
L35  ValueDisplayed: 1.5µH  [XAL7030]  (hidden comment: XAL7030-152MEB)
Q1  CSD15571Q2  [DQK0006C]
R164  ValueDisplayed: 1.00M  [0603]  (hidden comment: CRCW06031M00FKEA)
R166  ValueDisplayed: 45.3k  [0603]  (hidden comment: CRCW060345K3FKEA)
R167  ValueDisplayed: 10.0k  [0603]  (hidden comment: CRCW060310K0FKEA)
R169  ValueDisplayed: 100k  [0603]  (hidden comment: CRCW0603100KFKEA)
R170  ValueDisplayed: 0  [0402]  (hidden comment: ERJ-2GE0R00X)
R171  ValueDisplayed: 0  [0402]  (hidden comment: ERJ-2GE0R00X)
R174  ValueDisplayed: 0  [0402]  (hidden comment: ERJ-2GE0R00X)
R175  ValueDisplayed: 0  [0402]  (hidden comment: ERJ-2GE0R00X)
R176  ValueDisplayed: 0  [0402]  (hidden comment: ERJ-2GE0R00X)
R177  ValueDisplayed: 0  [0402]  (hidden comment: ERJ-2GE0R00X)
R179  ValueDisplayed: 0  [0402]  (hidden comment: ERJ-2GE0R00X)
R180  ValueDisplayed: 0  [0402]  (hidden comment: ERJ-2GE0R00X)
R220  ValueDisplayed: 1.00k  [0603]  (hidden comment: CRCW06031K00FKEA)
R221  ValueDisplayed: 33.2k  [0603]  (hidden comment: CRCW060333K2FKEA)
R222  ValueDisplayed: 1.00k  [0603]  (hidden comment: CRCW06031K00FKEA)
R223  ValueDisplayed: 1.00k  [0603]  (hidden comment: CRCW06031K00FKEA)
R224  ValueDisplayed: 1.00k  [0603]  (hidden comment: CRCW06031K00FKEA)
R226  ValueDisplayed: 48.7k  [0603]  (hidden comment: CRCW060348K7FKEA)
R228  ValueDisplayed: 51.1  [0603]  (hidden comment: CRCW060351R1FKEA)
R229  ValueDisplayed: 100k  [0603]  (hidden comment: RG1608P-104-B-T5)
R230  ValueDisplayed: 31.6k  [0603]  (hidden comment: CRCW060331K6FKEA)
R231  ValueDisplayed: 4.99k  [0603]  (hidden comment: CRCW06034K99FKEA)
R232  ValueDisplayed: 182k  [0603]  (hidden comment: CRCW0603182KFKEA)
R259  ValueDisplayed: 0  [0402]  (hidden comment: CRCW04020000Z0ED)
R260  ValueDisplayed: 0  [0402]  (hidden comment: CRCW04020000Z0ED)
R261  ValueDisplayed: 0  [0402]  (hidden comment: CRCW04020000Z0ED)
R294  ValueDisplayed: 47.5k  [0603]  (hidden comment: ERJ-3EKF4752V)
R295  ValueDisplayed: 0  [0402]  (hidden comment: ERJ-2GE0R00X)
R325  ValueDisplayed: 0  [0402]  (hidden comment: CRCW04020000Z0ED)
R326  ValueDisplayed: 100k  [0402]  (hidden comment: CRCW0402100KFKED)
R329  ValueDisplayed: 0  [0402]  (hidden comment: CRCW04020000Z0ED)
R331  ValueDisplayed: 25.5k  [0603]  (hidden comment: CRCW060325K5FKEA)
R332  ValueDisplayed: 11.8k  [0603]  (hidden comment: CRCW060311K8FKEA)
R342  ValueDisplayed: 1.00k  [0603]  (hidden comment: CRCW06031K00FKEA)
S5  L101011MS02Q  [SW_ L101011MS02Q]  (value not drawn)
TP1  5000  [Keystone5000]  (value not drawn)
TP2  5000  [Keystone5000]  (value not drawn)
TP4  5010  [Keystone5010]  (value not drawn)
TP5  5010  [Keystone5010]  (value not drawn)
TP6  5012  [Keystone5012]  (value not drawn)
TP7  5011  [Keystone5011]  (value not drawn)
TP8  5000  [Keystone5000]  (value not drawn)
TP9  5000  [Keystone5000]  (value not drawn)
TP10  5000  [Keystone5000]  (value not drawn)
TP11  5000  [Keystone5000]  (value not drawn)
TP12  5000  [Keystone5000]  (value not drawn)
TP13  5000  [Keystone5000]  (value not drawn)
TP14  5000  [Keystone5000]  (value not drawn)
TP15  5000  [Keystone5000]  (value not drawn)
TP16  5000  [Keystone5000]  (value not drawn)
TP20  5000  [Keystone5000]  (value not drawn)
U8  TPS259250DRCT  [DRC0010J]
U9  TPS54318RTE  [RTE-16]
U10  TPS7A4700RGWR  [RGW0020A]
U11  TPS7A4700RGWR  [RGW0020A]
U12  TPS7A8300RGRR  [RGR0020A]
U17  NFM31PC276B0J3L  [Murata_NFM31P]  (value not drawn)
U22  TPS7A9001DSKR  [DSK0010A]

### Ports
PCLK1 (in), PCLK2 (in), VSNS (in), VSNS (out)

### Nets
5V: C131.1 D8.2 Q1.3(G) R164.2 S5.1 TP4.1 U8.3(VIN) U8.4(VIN) U8.5(VIN)
5VIN: C127.1 C128.1 D9.1(K) L30.1 L31.1 L33.1 L34.2 TP5.1 U8.6(OUT) U8.7(OUT) U8.8(OUT)
+2.5V: C206.1 C207.2 R326.1 R331.2 R342.2 U22.1(OUT) U22.2(OUT)
+3.3V_ALL: C123.2 C194.2 C195.2 L18.1 L19.1 L22.1 L24.1 L26.1 L28.2 L29.2 L32.2 R220.2 R228.2 U17.3
+3.3V_LMX: C158.1 C159.2 C160.1 C161.1 L24.2 L25.2 TP11.1
+3.3V_LMXRF: C163.2 C164.1 C182.2 C183.1 L26.2 L27.2 TP12.1
+3.3V_VCO: C146.1 C147.2 C148.1 C149.1 L19.2 L21.2 R222.2 TP9.1
+3.3VLMK: C152.2 C153.1 C196.1 C197.1 C205.1 L22.2 L23.2 R325.1 TP10.1 U22.7(EN) U22.9(IN) U22.10(IN)
GND: C40.2 C42.2 C43.2 C73.2 C74.2 C75.2 C123.1 C127.2 C128.2 C129.2 C132.2 C133.2 C134.2 C135.2 C136.2 C137.2 C138.2 C139.2 C140.2 C141.2 C142.2 C143.1 C144.2 C145.2 C146.2 C147.1 C148.2 C149.2 C150.2 C151.2 C152.1 C153.2 C154.2 C155.2 C156.2 C157.2 C158.2 C159.1 C160.2 C161.2 C163.1 C164.2 C180.1 C181.1 C182.1 C183.2 C194.1 C195.1 C196.2 C197.2 C205.2 C206.2 C208.2 D9.2(A) D11.2(K) D13.2(K) D14.2(K) D15.2(K) D17.2(K) J6.2 J6.3 J6.4 J6.5 Q1.4(S) Q1.7(S) R167.1 R169.1 R170.1 R171.1 R174.1 R175.1 R176.1 R177.1 R179.1 R180.1 R221.2 R230.1 R232.1 R295.1 R329.2 R332.1 TP1.1 TP2.1 TP16.1 U8.11(PAD) U9.3(GND) U9.4(GND) U9.5(AGND) U9.17(PWPD) U10.7(GND) U10.21(PAD) U11.7(GND) U11.21(PAD) U12.8(GND) U12.18(GND) U12.21(PAD) U17.2 U22.4(GND) U22.11(PAD)
PGND: C131.2 D8.1 J25.2 J25.3 Q1.1(D) Q1.2(D) Q1.5(D) Q1.6(D) Q1.8(D) TP7.1
VDDD33: C142.1 C143.2 C144.1 C145.1 L18.2 L20.2 TP8.1
EN/UVLO: C132.1 R164.1 R167.2 TP6.1 U8.2(EN/UVLO)
ILIM: R166.2 U8.10(ILIM)
PCLK: J6.1 R260.1
PCLK1: R259.2 ; port PCLK1
PCLK2: R261.2 ; port PCLK2
VSNS: R229.1 R230.2 U9.6(VSNS) ; port VSNS
NetC40_1: C40.1 C129.1 L34.1 R226.1 U9.1(VIN) U9.2(VIN) U9.16(VIN)
NetC41_1: C41.1 U9.13(BOOT)
NetC41_2: C41.2 L35.1 TP13.1 U9.10(PH) U9.11(PH) U9.12(PH)
NetC42_1: C42.1 C43.1 C73.1 L35.2 U17.1
NetC74_1: C74.1 TP15.1 U9.9(SS)
NetC75_1: C75.1 R231.1
NetC133_1: C133.1 U8.1(DV/DT)
NetC134_1: C134.1 L28.1 L30.2 U10.13(EN) U10.15(IN) U10.16(IN)
NetC135_1: C135.1 C136.1 C137.1 L20.1 L23.1 R223.2 U10.1(OUT) U10.3(SENSE) U10.20(OUT)
NetC138_1: C138.1 L29.1 L31.2 U11.13(EN) U11.15(IN) U11.16(IN)
NetC139_1: C139.1 C140.1 C141.1 L21.1 U11.1(OUT) U11.3(SENSE) U11.20(OUT)
NetC150_1: C150.1 U10.14(NR)
NetC151_1: C151.1 U11.14(NR)
NetC154_1: C154.1 L32.1 L33.2 U12.14(EN) U12.15(IN) U12.16(IN) U12.17(IN)
NetC155_1: C155.1 C156.1 C157.1 C162.1 L25.1 L27.1 R224.2 R294.2 U12.1(OUT) U12.2(SNS) U12.19(OUT) U12.20(OUT)
NetC162_2: C162.2 U12.3(FB)
NetC175_1: C175.1 R232.2 U9.8(RT/CLK)
NetC175_2: C175.2 R259.1 R260.2 R261.1
NetC180_2: C180.2 U12.12(BIAS)
NetC181_2: C181.2 U12.13(NR/SS)
NetC207_1: C207.1 R331.1 R332.2 U22.3(FB)
NetC208_1: C208.1 U22.8(NR/SS)
NetD11_1: D11.1(A) R220.1
NetD13_1: D13.1(A) R222.1
NetD14_1: D14.1(A) R223.1
NetD15_1: D15.1(A) R224.1
NetD17_1: D17.1(A) R342.1
NetJ25_1: J25.1 S5.2
NetR166_1: R166.1 R169.2
NetR170_2: R170.2 U10.8(1P6V)
NetR171_2: R171.2 U11.8(1P6V)
NetR174_2: R174.2 U10.11(0P2V)
NetR175_2: R175.2 U11.11(0P2V)
NetR176_2: R176.2 U10.12(0P1V)
NetR177_2: R177.2 U11.12(0P1V)
NetR179_2: R179.2 U12.11(1.6_V)
NetR180_2: R180.2 U12.10(800_mV)
NetR221_1: R221.1 R226.2 U9.15(EN)
NetR228_1: R228.1 R229.2 TP14.1
NetR231_2: R231.2 U9.7(COMP)
NetR294_1: R294.1 U12.4(PG)
NetR295_2: R295.2 U12.6(100_mV)
NetR325_2: R325.2 R329.1 U22.6(SS_CTRL)
NetR326_2: R326.2 TP20.1 U22.5(PG)

Not connected (* = marked no-connect by the designer): U8 9(NC); U9 14(PWRGD)*; U10 2(NC)* 4(6P4V2)* 5(6P4V1)* 6(3P2V)* 9(0P8V)* 10(0P4V)* 17(NC)* 18(NC)* 19(NC)*; U11 2(NC)* 4(6P4V2)* 5(6P4V1)* 6(3P2V)* 9(0P8V)* 10(0P4V)* 17(NC)* 18(NC)* 19(NC)*; U12 5(50_mV)* 7(200_mV)* 9(400_mV)*

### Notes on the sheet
- +3.3V, |.3A
- (near U10) +3.3V, ~930mA
- (near U11) +3.3V, |60mA
- (near U12) +3.3V,
  .1A

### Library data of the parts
C40 C41 C135 C139 C144 C148 C153 C155 C160 C162 C164 C175 C181 = GRM155R71C104KA88D: CAP, CERM, 0.1 µF, 16 V, +/- 10%, X7R, 0402; Manufacturer: MuRata; Polarized: N; CompType: Capacitor; Value: 0.1uF; U/M: EA; Cap_F: 0.0000001; Tolerance_%: 10; Value1: Unknown; VDC_V: 16; Value2: 16V; TaMin_C: -55; TaMax_C: 125; SizeArea_mm2: 0.5; SizeAreaWB_mm2: 3; SizeX_mm: 1; SizeZ_mm: 0.6; AEC Category: Q200
C42 C43 C73 = 885012208019: CAP, CERM, 22 µF, 10 V, +/- 10%, X7R, 1206_190; Manufacturer: Wurth Elektronik; Polarized: N; CompType: Capacitor; Value: 22uF; U/M: EA; Cap_F: 0.000022; Tolerance_%: 10; Value1: Unknown; Value2: 10V; TaMin_C: -55; TaMax_C: 125; Cap_Case: 1206; SizeArea_mm2: 5.12; SizeAreaWB_mm2: 10.92; SizeX_mm: 3.2; SizeY_mm: 1.6; SizeZ_mm: 1.9; AEC Category: Q200
C74 C145 C149 C197 = GRM155R71E103KA01D: as C116 on sheet TIDA-010131-E3_USB
C75 = GRM188R71E103KA01D: CAP, CERM, 0.01 µF, 25 V, +/- 10%, X7R, 0603; Manufacturer: MuRata; Polarized: N; CompType: Capacitor; Value: 0.01uF; U/M: EA; Cap_F: 0.00000001; Tolerance_%: 10; Value1: Unknown; VDC_V: 25; Value2: 25V; TaMin_C: -55; TaMax_C: 125; SizeArea_mm2: 1.28; SizeAreaWB_mm2: 4.68; SizeX_mm: 1.6; SizeY_mm: 0.8; SizeZ_mm: 1; AEC Category: Q200
C123 C134 C138 C143 C147 C152 C154 C159 C163 C180 C182 C194 C195 = GRM188R61A106ME69D: as C106 on sheet TIDA-010131-E3_USB
C127 C128 C131 = 08053D105KAT2A: CAP, CERM, 1 µF, 25 V, +/- 10%, X5R, 0805; Manufacturer: AVX; Polarized: N; CompType: Capacitor; Value: 1uF; U/M: EA; Cap_F: 0.000001; Tolerance_%: 10; ESR_ohm: 0.012; Value1: 0.012 ohm; VDC_V: 25; Value2: 25V; TaMin_C: -55; TaMax_C: 85; Cap_Case: 0805; SizeArea_mm2: 2.5; SizeAreaWB_mm2: 6.75; SizeX_mm: 2; SizeY_mm: 1.25; SizeZ_mm: 1.45; AEC Category: Q200
C129 = GRM188R61A106ME69D: CAP, CERM, 10 µF, 10 V, +/- 20%, X5R, 0603; Manufacturer: MuRata; Polarized: N; CompType: Capacitor; Value: 10uF; U/M: EA; Cap_F: 0.00001; Tolerance_%: 20; Value1: Unknown; VDC_V: 10; Value2: 10V; TaMin_C: -55; TaMax_C: 85; SizeArea_mm2: 1.28; SizeAreaWB_mm2: 4.68; SizeX_mm: 1.6; SizeY_mm: 0.8; SizeZ_mm: 1; AEC Category: Q200; Green_Lifecycle: Active; Green_REACh: Passed
C132 C133 = 06031C102MAT2A: CAP, CERM, 1000 pF, 100 V, +/- 20%, X7R, 0603; Manufacturer: AVX; Polarized: N; CompType: Capacitor; Value: 1000pF; U/M: EA; Cap_F: 0.000000001; Tolerance_%: 20; ESR_ohm: 0.276; Value1: 0.276 ohm; VDC_V: 100; Value2: 100V; TaMin_C: -55; TaMax_C: 125; SizeArea_mm2: 1.28; SizeAreaWB_mm2: 4.68; SizeX_mm: 1.6; SizeY_mm: 0.8; SizeZ_mm: 1; AEC Category: Q200
C136 C140 C150 C151 C156 C161 C183 = C1005X7S1A105K050BC: CAP, CERM, 1 µF, 10 V, +/- 10%, X7S, 0402; Manufacturer: TDK; Polarized: N; CompType: Capacitor; Value: 1uF; U/M: EA; Cap_F: 0.000001; Tolerance_%: 10; ESR_ohm: 0.011416; Value1: 0.011416 ohm; Value2: 10V; IRMS_A: 1.483; TaMin_C: -55; TaMax_C: 125; SizeArea_mm2: 0.5; SizeAreaWB_mm2: 3; SizeX_mm: 1; SizeZ_mm: 0.6; AEC Category: Q200
C137 C141 C157 = C3225X5R1A476M250AC: CAP, CERM, 47 µF, 10 V, +/- 20%, X5R, 1210; Manufacturer: TDK; Polarized: N; CompType: Capacitor; Value: 47uF; U/M: EA; Cap_F: 0.000047; Tolerance_%: 20; ESR_ohm: 0.003602; Value1: 0.003602 ohm; VDC_V: 10; Value2: 10V; IRMS_A: 3.87414; TaMin_C: -55; TaMax_C: 85; SizeArea_mm2: 8; SizeAreaWB_mm2: 14.7; SizeX_mm: 3.2; SizeY_mm: 2.5; SizeZ_mm: 2.8; AEC Category: Q200
C142 C146 C158 C196 = C2012X5R1A336M125AC: CAP, CERM, 33 µF, 10 V, +/- 20%, X5R, 0805; Manufacturer: TDK; Polarized: N; CompType: Capacitor; Value: 33uF; U/M: EA; Cap_F: 0.000033; Tolerance_%: 20; ESR_ohm: 0.001694; Value1: 0.001694 ohm; VDC_V: 10; Value2: 10V; IRMS_A: 5.01281; TaMin_C: -55; TaMax_C: 85; Cap_Case: 0805; SizeArea_mm2: 2.5; SizeAreaWB_mm2: 6.75; SizeX_mm: 2; SizeY_mm: 1.25; SizeZ_mm: 1.45; AEC Category: Q200
C205 C206 = GRM188R61C106MAALD: CAP, CERM, 10 µF, 16 V,+/- 20%, X5R, 0603; Manufacturer: MuRata; Polarized: N; CompType: Capacitor; Value: 10uF; U/M: EA; Cap_F: 0.00001; Tolerance_%: 20; VDC_V: 16; Value2: 16V; TaMin_C: -55; TaMax_C: 85; SizeArea_mm2: 1.28; SizeAreaWB_mm2: 4.68; SizeX_mm: 1.6; SizeY_mm: 0.8; SizeZ_mm: 1; AEC Category: Q200; Green_Lifecycle: Active; Green_REACh: Passed
C207 = GRM188R71C103KA01D: CAP, CERM, 0.01 µF, 16 V,+/- 10%, X7R, 0603; Manufacturer: MuRata; Polarized: N; CompType: Capacitor; Value: 0.01uF; U/M: EA; Cap_F: 0.00000001; Tolerance_%: 10; VDC_V: 16; Value2: 16V; TaMin_C: -55; TaMax_C: 125; SizeArea_mm2: 1.28; SizeAreaWB_mm2: 4.68; SizeX_mm: 1.6; SizeY_mm: 0.8; SizeZ_mm: 1; AEC Category: Q200; Green_Lifecycle: Active; Green_REACh: Passed
C208 = CL10B104KO8NNNC: CAP, CERM, 0.1 µF, 16 V,+/- 10%, X7R, 0603; Manufacturer: Samsung Electro-Mechanics; Polarized: N; CompType: Capacitor; Value: 0.1uF; U/M: EA; Cap_F: 0.0000001; Tolerance_%: 10; VDC_V: 16; Value2: 16V; TaMin_C: -55; TaMax_C: 125; SizeArea_mm2: 1.28; SizeAreaWB_mm2: 4.68; SizeX_mm: 1.6; SizeY_mm: 0.8; SizeZ_mm: 1; AEC Category: Q200; Green_Lifecycle: Active; Green_REACh: Passed
D8 = SMBJ15CA: Diode, TVS, Bi, 15 V, 24.4 Vc, SMB; Manufacturer: Fairchild Semiconductor; U/M: EA; Vr_V: 15; Value1: W; AEC Category: Q101
D9 = MBR130T1G: Diode, Schottky, 30 V, 1 A, SOD-123; Manufacturer: ON Semiconductor; U/M: EA; Vf_V: 0.47; Value: 30V; Value1: 1A; Value2: 0.47V; Io_A: 1; Vr_V: 30; TJmax_C: 125; RJC_CperW: 108; SizeAreaWB_mm2: 13.095; SizeArea_mm2: 6.545; SizeX_mm: 3.85; SizeY_mm: 1.7; SizeZ_mm: 1.35; AEC Category: Q101
D11 D13-D15 D17 = LTST-C191TGKT: as D10 on sheet TIDA-010131-E3_USB
J6 = 142-0701-201: Connector, TH, SMA; Manufacturer: Emerson Network Power; SymbolCreator: X0208326
J25 = RAPC722X: Power Jack, mini, 2.1mm OD, R/A, TH; Manufacturer: Switchcraft; SymbolCreator: a0799628
L18-L34 = BLM31PG121SN1L: as L15 on sheet TIDA-010131-E3_USB
L35 = XAL7030-152MEB: Inductor, Shielded, Composite, 1.5 µH, 15 A, 0.0076 ohm, SMD; Manufacturer: Coilcraft; Value: 1.5uH; Ind_H: 1.5E-6; Imax_A: 15; Irms: 15A @ 40C rise; Isat: 23.5A @ 0.7% inductance drop; DCR_ohm: 0.0076; Value2: 15A; SizeAreaWB_mm2: 100; SizeArea_mm2: 64; SizeX_mm: 8; SizeZ_mm: 3.1; AEC Category: Q200
Q1 = CSD15571Q2: MOSFET, N-CH, 20 V, 10 A, DQK0006C (WSON-6); Manufacturer: Texas Instruments; Alternate Manufacturer: None; U/M: EA; ChType: N; Value: 20V; VdsMax_V: 20; Value1: 19.2 ohm; Rdson45_ohm: 19.2; Value2: 2.5 nC; QgTyp_nC: 2.5; IdsMax_A: 10; SizeAreaWB_mm2: 9; SizeArea_mm2: 4; SizeX_mm: 2; SizeZ_mm: 0.8; AEC Category: Q101
R164 = CRCW06031M00FKEA: RES, 1.00 M, 1%, 0.1 W, 0603; Manufacturer: Vishay-Dale; CompType: Resistor; Value: 1.00Meg; Res_ohm: 1000000; Value_Code: 1M00; Tolerance_%: 1; Power_W: 0.1; Value2: 0.1W; VDC_V: 75; TempCo: 100 ppm/C; SizeArea_mm2: 1.28; SizeX_mm: 1.6; SizeY_mm: 0.8; EIA_Code: E96; U/M: EA; AEC Category: Q200
R166 = CRCW060345K3FKEA: RES, 45.3 k, 1%, 0.1 W, 0603; Manufacturer: Vishay-Dale; CompType: Resistor; Value: 45.3k; Res_ohm: 45300; Value_Code: 45k3; Tolerance_%: 1; Power_W: 0.1; Value2: 0.1W; VDC_V: 75; TempCo: 100 ppm/C; SizeArea_mm2: 1.28; SizeX_mm: 1.6; SizeY_mm: 0.8; EIA_Code: E96; U/M: EA; AEC Category: Q200
R167 = CRCW060310K0FKEA: RES, 10.0 k, 1%, 0.1 W, 0603; Manufacturer: Vishay-Dale; CompType: Resistor; Value: 10.0k; Res_ohm: 10000; Value_Code: 10k0; Tolerance_%: 1; Power_W: 0.1; Value2: 0.1W; VDC_V: 75; TempCo: 100 ppm/C; SizeArea_mm2: 1.28; SizeX_mm: 1.6; SizeY_mm: 0.8; EIA_Code: E96; U/M: EA; AEC Category: Q200
R169 = CRCW0603100KFKEA: RES, 100 k, 1%, 0.1 W, 0603; Manufacturer: Vishay-Dale; CompType: Resistor; Value: 100k; Res_ohm: 100000; Tolerance_%: 1; Power_W: 0.1; Value2: 0.1W; VDC_V: 75; TempCo: 100 ppm/C; SizeArea_mm2: 1.28; SizeX_mm: 1.6; SizeY_mm: 0.8; EIA_Code: E96; U/M: EA; AEC Category: Q200
R170 R171 R174-R177 R179 R180 R295 = ERJ-2GE0R00X: RES, 0, 5%, 0.063 W, 0402; Manufacturer: Panasonic; CompType: Resistor; Value: 0; Value_Code: 0000; Tolerance_%: 5; Power_W: 0.063; Value2: 0.063W; VDC_V: 50; TempCo: 600 ppm/C; SizeArea_mm2: 0.5; SizeX_mm: 1; SizeZ_mm: 0.6; EIA_Code: E24; U/M: EA; AEC Category: Q200
R220 R222-R224 R342 = CRCW06031K00FKEA: as R217 on sheet TIDA-010131-E3_USB
R221 = CRCW060333K2FKEA: RES, 33.2 k, 1%, 0.1 W, 0603; Manufacturer: Vishay-Dale; CompType: Resistor; Value: 33.2k; Res_ohm: 33200; Value_Code: 33k2; Tolerance_%: 1; Power_W: 0.1; Value2: 0.1W; VDC_V: 75; TempCo: 100 ppm/C; SizeArea_mm2: 1.28; SizeX_mm: 1.6; SizeY_mm: 0.8; EIA_Code: E96; U/M: EA; AEC Category: Q200
R226 = CRCW060348K7FKEA: RES, 48.7 k, 1%, 0.1 W, 0603; Manufacturer: Vishay-Dale; CompType: Resistor; Value: 48.7k; Res_ohm: 48700; Value_Code: 48k7; Tolerance_%: 1; Power_W: 0.1; Value2: 0.1W; VDC_V: 75; TempCo: 100 ppm/C; SizeArea_mm2: 1.28; SizeX_mm: 1.6; SizeY_mm: 0.8; EIA_Code: E96; U/M: EA; AEC Category: Q200
R228 = CRCW060351R1FKEA: RES, 51.1, 1%, 0.1 W, 0603; Manufacturer: Vishay-Dale; CompType: Resistor; Value: 51.1; Value_Code: 51R1; Tolerance_%: 1; Power_W: 0.1; Value2: 0.1W; VDC_V: 75; TempCo: 100 ppm/C; SizeArea_mm2: 1.28; SizeX_mm: 1.6; SizeY_mm: 0.8; EIA_Code: E96; U/M: EA; AEC Category: Q200
R229 = RG1608P-104-B-T5: RES, 100 k, 0.1%, 0.1 W, 0603; Manufacturer: Susumu Co Ltd; CompType: Resistor; Value: 100k; Res_ohm: 100000; Tolerance_%: 0.1; Value2: 0.1W; VDC_V: 75; TempCo: 25 ppm/C; SizeArea_mm2: 1.28; SizeX_mm: 1.6; SizeY_mm: 0.8; SizeZ_mm: 1; EIA_Code: E192; U/M: EA; AEC Category: Q200
R230 = CRCW060331K6FKEA: RES, 31.6 k, 1%, 0.1 W, 0603; Manufacturer: Vishay-Dale; CompType: Resistor; Value: 31.6k; Res_ohm: 31600; Value_Code: 31k6; Tolerance_%: 1; Power_W: 0.1; Value2: 0.1W; VDC_V: 75; TempCo: 100 ppm/C; SizeArea_mm2: 1.28; SizeX_mm: 1.6; SizeY_mm: 0.8; EIA_Code: E96; U/M: EA; AEC Category: Q200
R231 = CRCW06034K99FKEA: RES, 4.99 k, 1%, 0.1 W, 0603; Manufacturer: Vishay-Dale; CompType: Resistor; Value: 4.99k; Res_ohm: 4990; Value_Code: 4k99; Tolerance_%: 1; Power_W: 0.1; Value2: 0.1W; VDC_V: 75; TempCo: 100 ppm/C; SizeArea_mm2: 1.28; SizeX_mm: 1.6; SizeY_mm: 0.8; EIA_Code: E96; U/M: EA; AEC Category: Q200
R232 = CRCW0603182KFKEA: RES, 182 k, 1%, 0.1 W, 0603; Manufacturer: Vishay-Dale; CompType: Resistor; Value: 182k; Res_ohm: 182000; Tolerance_%: 1; Power_W: 0.1; Value2: 0.1W; VDC_V: 75; TempCo: 100 ppm/C; SizeArea_mm2: 1.28; SizeX_mm: 1.6; SizeY_mm: 0.8; EIA_Code: E96; U/M: EA; AEC Category: Q200
R259-R261 = CRCW04020000Z0ED: as R172 on sheet TIDA-010131-E3_USB
R294 = ERJ-3EKF4752V: RES, 47.5 k, 1%, 0.1 W, AEC-Q200 Grade 0, 0603; Manufacturer: Panasonic; CompType: Resistor; Value: 47.5k; Res_ohm: 47500; Value_Code: 47k5; Tolerance_%: 1; Power_W: 0.1; Value2: 0.1W; VDC_V: 50; TempCo: 100 ppm/C; SizeArea_mm2: 1.28; SizeX_mm: 1.6; SizeY_mm: 0.8; EIA_Code: E96; U/M: EA; AEC Category: Q200; AEC Qualified: Y; AEC Grade: 0
R325 = CRCW04020000Z0ED: RES, 0, 5%, 0.063 W, 0402; Manufacturer: Vishay-Dale; CompType: Resistor; Value: 0; Value_Code: 0000; Tolerance_%: 5; Power_W: 0.063; Value2: 0.063W; VDC_V: 50; TempCo: 200 ppm/C; SizeArea_mm2: 0.5; SizeX_mm: 1; SizeZ_mm: 0.6; EIA_Code: E24; U/M: EA; AEC Category: Q200; Green_Lifecycle: Active; Green_REACh: Passed
R326 = CRCW0402100KFKED: RES, 100 k, 1%, 0.063 W, 0402; Manufacturer: Vishay-Dale; CompType: Resistor; Value: 100k; Res_ohm: 100000; Tolerance_%: 1; Power_W: 0.063; Value2: 0.063W; VDC_V: 50; TempCo: 100 ppm/C; SizeArea_mm2: 0.5; SizeZ_mm: 0.6; EIA_Code: E96; U/M: EA; AEC Category: Q200; Green_Lifecycle: Active; Green_REACh: Passed
R329 = CRCW04020000Z0ED: as R335 on sheet TIDA-010131-E3_USB
R331 = CRCW060325K5FKEA: RES, 25.5 k, 1%, 0.1 W, 0603; Manufacturer: Vishay-Dale; CompType: Resistor; Value: 25.5k; Res_ohm: 25500; Value_Code: 25k5; Tolerance_%: 1; Power_W: 0.1; Value2: 0.1W; VDC_V: 75; TempCo: 100 ppm/C; SizeArea_mm2: 1.28; SizeX_mm: 1.6; SizeY_mm: 0.8; EIA_Code: E96; U/M: EA; AEC Category: Q200; Green_Lifecycle: Active; Green_REACh: Passed
R332 = CRCW060311K8FKEA: RES, 11.8 k, 1%, 0.1 W, 0603; Manufacturer: Vishay-Dale; CompType: Resistor; Value: 11.8k; Res_ohm: 11800; Value_Code: 11k8; Tolerance_%: 1; Power_W: 0.1; Value2: 0.1W; VDC_V: 75; TempCo: 100 ppm/C; SizeArea_mm2: 1.28; SizeX_mm: 1.6; SizeY_mm: 0.8; EIA_Code: E96; U/M: EA; AEC Category: Q200; Green_Lifecycle: Active; Green_REACh: Passed
S5 = L101011MS02Q: SWITCH SLIDE SPST 4A PCB, TH; Manufacturer: C&K Components; Symbol Creator: a0411947; VDC_V: 125; SwitchFunction: Off-On; PositionCount: 1; CurrentRating_mA: 4000
TP1 TP2 TP8-TP16 TP20 = 5000: as VCCCORE on sheet TIDA-010131-E3_USB
TP4 TP5 = 5010: Test Point, Multipurpose, Red, TH; Manufacturer: Keystone; CompType: Test Point Loop; ContactFinish: Silver
TP6 = 5012: Test Point, Multipurpose, White, TH; Manufacturer: Keystone; CompType: Test Point Loop; ContactFinish: Silver
TP7 = 5011: Test Point, Multipurpose, Black, TH; Manufacturer: Keystone; CompType: Test Point Loop; ContactFinish: Silver
U8 = TPS259250DRCR: 5V, 5A, 30mΩ eFuse with Adjustable +/-15% Accurate Current Limit, DRC0010J (VSON-10); Manufacturer: Texas Instruments; SymbolCreator: Altium; SizeArea_mm2: 9; SizeAreaWB_mm2: 16; SizeX_mm: 3; SizeZ_mm: 1; CompType: IC; U/M: EA
U9 = TPS54318RTE: IC, 2.95V To 6V Input, 3A Output, 2MHz, Synchronous SWIFT; Manufacturer: TI; Alternate Manufacturer: None; Area: 33865
U10 U11 = TPS7A4700RGWR: 36-V, 1-A, 4.17-μVRMS, RF LDO Voltage Regulator, RGW0020A (VQFN-20); Alternate PartNumber: TPS7A4700RGWT; Manufacturer: Texas Instruments; SymbolCreator: a0412235; SizeArea_mm2: 25; SizeAreaWB_mm2: 49; SizeX_mm: 5; SizeZ_mm: 1; CompType: IC; U/M: EA
U12 = TPS7A8300ARGRR: 2-A, 6-uVRMS, RF, LDO Voltage Regulator, RGR0020A (VQFN-20); Manufacturer: Texas Instruments; SymbolCreator: a0411947; SizeArea_mm2: 12.25; SizeAreaWB_mm2: 20.25; SizeX_mm: 3.5; SizeZ_mm: 1; CompType: IC; U/M: EA
U17 = NFM31PC276B0J3L: FILTER LC HIGH FREQ 27uF 1206; Manufacturer: MuRata; SymbolCreator: Altium
U22 = CMP-0077752-1: 500mA High-Accuracy Low-Noise Low-Dropout (LDO) Voltage Regulator, DSK0010A (WSON-10); Alternate PartNumber: TPS7A9001DSKT; Alternate Manufacturer: Texas Instruments; SizeAreaWB_mm2: 12.25; SizeZ_mm: 0.8; SizeX_mm: 2.5; SizeArea_mm2: 6.25; CompType: IC; AEC Qualified: N; AEC Category: Q200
